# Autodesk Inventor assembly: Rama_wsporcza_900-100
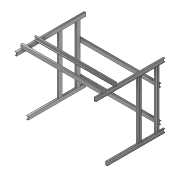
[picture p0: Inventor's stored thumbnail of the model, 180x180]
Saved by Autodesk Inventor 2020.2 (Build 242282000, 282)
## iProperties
Created: 2015-01
Part Number: Rama_wsporcza_900-100
Document SubType Name: Konstrukcja spawana
Designer: F.Stasiak
Mass: 71003.8 g
Surface Area: 30663.3 cm^2
Volume: 9045.07 cm^3
Density: 7.85 g/cm^3
Weld Material: Stal, miękka, spawana
Description: Rama wsporcza
Catalog Web Link: www.expertbooks.pl
Manager: www.cadconsulting.pl
Company: Fabian Stasiak CAD Consulting
Author: F.Stasiak
Subject: Zbiór ćwiczeń. Autodesk Inventor 2020. Kurs Professional
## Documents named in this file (4)
- C:\2020_Kurs_Professional\R5 RamyMES\Rama_wsporcza_900-100.iam
- C:\2020_Kurs_Professional\R5 RamyMES\DIN1026 - U 60 - 1200.ipt
- C:\2020_Kurs_Professional\R5 RamyMES\DIN1026 - U 60 - 1400.ipt
- C:\2020_Kurs_Professional\R5 RamyMES\DIN1026 - U 60 - 1000.ipt
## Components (12 placed, 3 different names)
1. DIN1026 - U 60 - 1000:1 — Równoległy:21, Równoległy:22, Zestawiający:20, Zestawiający:21, Równoległy:23, Równoległy:25, Zestawiający:22, Równoległy:26, Równoległy:33
2. DIN1026 - U 60 - 1200:1 — Zestawiający:30, Równoległy:39, Równoległy:40, Równoległy:41
3. DIN1026 - U 60 - 1200:2 — Zestawiający:12, Równoległy:15, Zestawiający:13, Równoległy:21, Równoległy:22, Zestawiający:20, Równoległy:24, Równoległy:34, Równoległy:41
4. DIN1026 - U 60 - 1400:1 — Zestawiający:12, Równoległy:15, Zestawiający:14, Równoległy:16, Równoległy:34
5. DIN1026 - U 60 - 1400:2 — Zestawiający:13, Zestawiający:14, Równoległy:16
6. DIN1026 - U 60 - 1000:2 — Zestawiający:21, Równoległy:23, Równoległy:24, Równoległy:25, Zestawiający:23, Równoległy:28, Równoległy:42
7. DIN1026 - U 60 - 1000:3 — Zestawiający:22, Równoległy:26, Zestawiający:23
8. DIN1026 - U 60 - 1000:4 — Równoległy:28, Równoległy:30, Zestawiający:25, Równoległy:31, Zestawiający:26, Równoległy:32, Zestawiający:27, Równoległy:36, Równoległy:39
9. DIN1026 - U 60 - 1000:5 — Równoległy:30, Zestawiający:25, Równoległy:31, Zestawiający:30
10. DIN1026 - U 60 - 1000:6 — Zestawiający:26, Równoległy:32, Równoległy:33, Zestawiający:28, Równoległy:40
11. DIN1026 - U 60 - 1400:3 — Zestawiający:27, Równoległy:36, Zestawiający:28, Równoległy:37, Równoległy:38, Zestawiający:29, Równoległy:42
12. DIN1026 - U 60 - 1400:4 — Równoległy:37, Równoległy:38, Zestawiający:29
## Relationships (34: Flush 21, Mate 13)
- Zestawiający:12 [Mate]: DIN1026 - U 60 - 1200:2 ↔ DIN1026 - U 60 - 1400:1
- Równoległy:15 [Flush]: DIN1026 - U 60 - 1200:2 ↔ DIN1026 - U 60 - 1400:1
- Zestawiający:13 [Mate]: DIN1026 - U 60 - 1200:2 ↔ DIN1026 - U 60 - 1400:2
- Zestawiający:14 [Mate]: DIN1026 - U 60 - 1400:1 ↔ DIN1026 - U 60 - 1400:2
- Równoległy:16 [Flush]: DIN1026 - U 60 - 1400:1 ↔ DIN1026 - U 60 - 1400:2
- Równoległy:21 [Flush]: DIN1026 - U 60 - 1000:1 ↔ DIN1026 - U 60 - 1200:2
- Równoległy:22 [Flush]: DIN1026 - U 60 - 1000:1 ↔ DIN1026 - U 60 - 1200:2
- Zestawiający:20 [Mate]: DIN1026 - U 60 - 1000:1 ↔ DIN1026 - U 60 - 1200:2
- Zestawiający:21 [Mate]: DIN1026 - U 60 - 1000:1 ↔ DIN1026 - U 60 - 1000:2
- Równoległy:23 [Flush]: DIN1026 - U 60 - 1000:1 ↔ DIN1026 - U 60 - 1000:2
- Równoległy:24 [Flush]: DIN1026 - U 60 - 1200:2 ↔ DIN1026 - U 60 - 1000:2
- Równoległy:25 [Flush]: DIN1026 - U 60 - 1000:1 ↔ DIN1026 - U 60 - 1000:2
- Zestawiający:22 [Mate]: DIN1026 - U 60 - 1000:1 ↔ DIN1026 - U 60 - 1000:3
- Równoległy:26 [Flush]: DIN1026 - U 60 - 1000:1 ↔ DIN1026 - U 60 - 1000:3
- Zestawiający:23 [Mate]: DIN1026 - U 60 - 1000:2 ↔ DIN1026 - U 60 - 1000:3
- Równoległy:28 [Flush]: DIN1026 - U 60 - 1000:2 ↔ DIN1026 - U 60 - 1000:4
- Równoległy:30 [Flush]: DIN1026 - U 60 - 1000:4 ↔ DIN1026 - U 60 - 1000:5
- Zestawiający:25 [Mate]: DIN1026 - U 60 - 1000:4 ↔ DIN1026 - U 60 - 1000:5
- Równoległy:31 [Flush]: DIN1026 - U 60 - 1000:4 ↔ DIN1026 - U 60 - 1000:5
- Zestawiający:26 [Mate]: DIN1026 - U 60 - 1000:4 ↔ DIN1026 - U 60 - 1000:6
- Równoległy:32 [Flush]: DIN1026 - U 60 - 1000:4 ↔ DIN1026 - U 60 - 1000:6
- Równoległy:33 [Flush]: DIN1026 - U 60 - 1000:1 ↔ DIN1026 - U 60 - 1000:6
- Równoległy:34 [Flush]: DIN1026 - U 60 - 1200:2 ↔ DIN1026 - U 60 - 1400:1
- Zestawiający:27 [Mate]: DIN1026 - U 60 - 1000:4 ↔ DIN1026 - U 60 - 1400:3
- Równoległy:36 [Flush]: DIN1026 - U 60 - 1000:4 ↔ DIN1026 - U 60 - 1400:3
- Zestawiający:28 [Mate]: DIN1026 - U 60 - 1000:6 ↔ DIN1026 - U 60 - 1400:3
- Równoległy:37 [Flush]: DIN1026 - U 60 - 1400:3 ↔ DIN1026 - U 60 - 1400:4
- Równoległy:38 [Flush]: DIN1026 - U 60 - 1400:3 ↔ DIN1026 - U 60 - 1400:4
- Zestawiający:29 [Mate]: DIN1026 - U 60 - 1400:3 ↔ DIN1026 - U 60 - 1400:4
- Zestawiający:30 [Mate]: DIN1026 - U 60 - 1200:1 ↔ DIN1026 - U 60 - 1000:5
- Równoległy:39 [Flush]: DIN1026 - U 60 - 1200:1 ↔ DIN1026 - U 60 - 1000:4
- Równoległy:40 [Flush]: DIN1026 - U 60 - 1200:1 ↔ DIN1026 - U 60 - 1000:6
- Równoległy:41 [Flush]: DIN1026 - U 60 - 1200:1 ↔ DIN1026 - U 60 - 1200:2
- Równoległy:42 [Flush]: DIN1026 - U 60 - 1000:2 ↔ DIN1026 - U 60 - 1400:3
